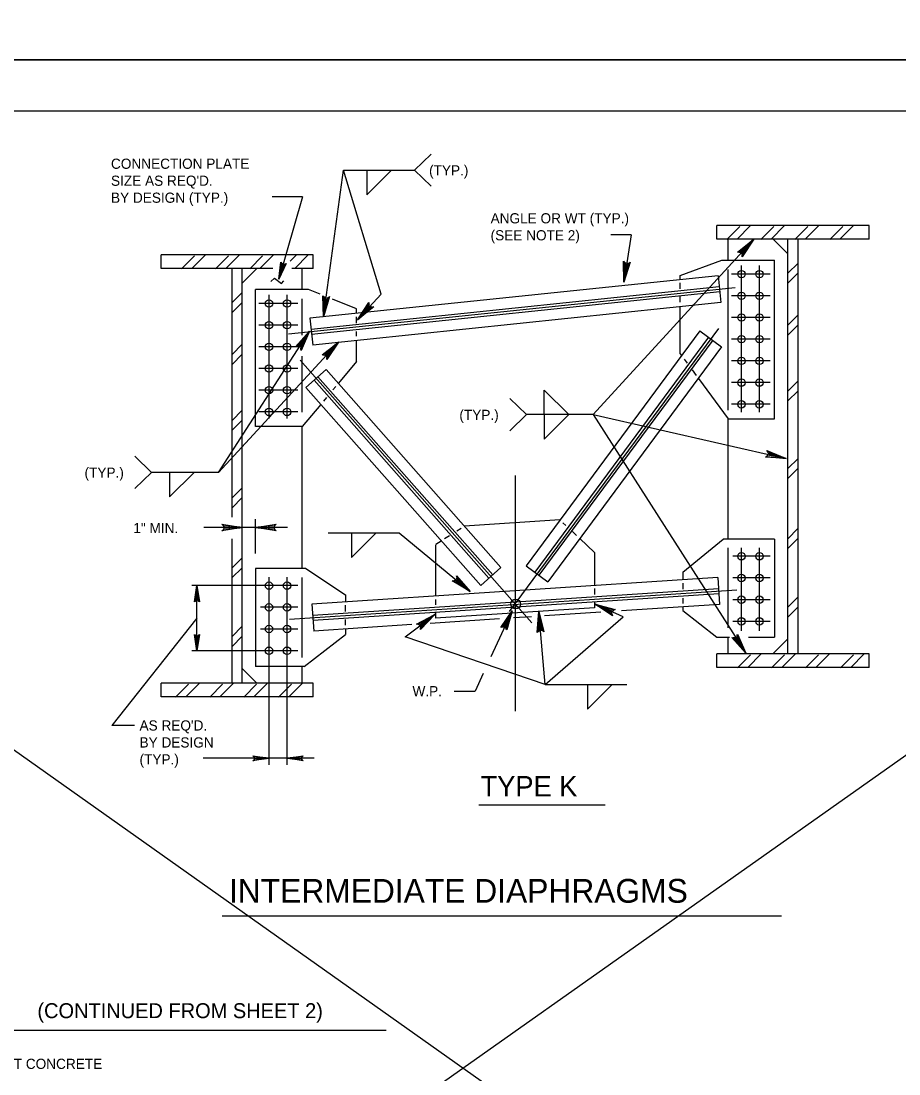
# Model space of a CAD drawing. Extents: x 634656 to 641360, y 298715 to 301183.
# Drawn here: x 634956.8 to 635215.5, y 299020.3 to 299330.4 of the extents above; entities that cross this region are included whole.
import ezdxf

# ---------------------------------------------------------------- set-up
doc = ezdxf.new("R2010")
doc.units = 0
for name, color, linetype in [('1', 7, 'Continuous'), ('2', 7, 'Continuous'), ('PLT-BNDY', 7, 'Continuous')]:
    doc.layers.add(name, color=color, linetype=linetype)

msp = doc.modelspace()

# ---------------------------------------------------------------- linework, layer by layer
at = {"layer": '1'}
for p, q in [((634656.46, 298718.13), (635518.79, 299326.83)), ((634661.92, 299322.77), (635521.53, 298714.94)), ((635045.96, 299243.34), (635051.84, 299286.49)), ((635063, 299249.96), (635051.84, 299286.49)), ((635051.84, 299286.49), (635072.82, 299286.49)), ((635039.82, 299278.64), (635032.8, 299254.4)), ((635206.76, 299270.17), (635161.92, 299270.17)), ((635161.92, 299266.17), (635161.92, 299270.17)), ((635168.63, 299269.89), (635164.81, 299266.08)), ((635171.83, 299270.17), (635167.83, 299266.17)), ((635178.66, 299269.89), (635174.85, 299266.08)), ((635181.86, 299270.17), (635177.86, 299266.17)), ((635188.69, 299269.89), (635184.88, 299266.08)), ((635191.9, 299270.17), (635187.9, 299266.17)), ((635198.96, 299269.89), (635195.15, 299266.08)), ((635202.17, 299270.17), (635198.17, 299266.17)), ((635206.76, 299266.17), (635206.76, 299270.17)), ((635125.47, 299214.49), (635172.79, 299266.16)), ((635136.63, 299267.42), (635134.46, 299253.48)), ((635206.76, 299266.17), (635161.92, 299266.17)), ((635165.17, 299260), (635165.17, 299266.17)), ((635182.84, 299261.84), (635178.52, 299266.17)), ((635182.84, 299144.06), (635182.84, 299266.17)), ((635185.84, 299144.06), (635185.84, 299266.17)), ((635042.94, 299261.53), (634998.1, 299261.53)), ((634998.1, 299257.53), (634998.1, 299261.53)), ((635011.16, 299261.53), (635007.17, 299257.53)), ((635021.2, 299261.53), (635017.2, 299257.53)), ((635031.23, 299261.53), (635027.23, 299257.53)), ((635038, 299261.53), (635036.16, 299259.69)), ((635041.5, 299261.53), (635037.5, 299257.53)), ((635042.94, 299257.53), (635042.94, 299261.53)), ((635007.96, 299261.25), (635004.15, 299257.44)), ((635017.99, 299261.25), (635014.18, 299257.44)), ((635028.03, 299261.25), (635024.22, 299257.44)), ((635151.11, 299255.46), (635163.37, 299260)), ((635163.37, 299260), (635178.89, 299260)), ((635169.12, 299215.26), (635169.12, 299258.45)), ((635174.43, 299215.26), (635174.43, 299258.45)), ((635178.89, 299213.23), (635178.89, 299260)), ((635185.84, 299259.14), (635182.84, 299256.13)), ((635030.99, 299257.53), (634998.1, 299257.53)), ((635019.02, 299184.26), (635019.02, 299257.53)), ((635022.02, 299253.2), (635026.35, 299257.53)), ((635022.02, 299135.42), (635022.02, 299257.53)), ((635042.94, 299257.53), (635036.65, 299257.53)), ((635039.69, 299251.36), (635039.69, 299257.53)), ((635162.27, 299255.42), (635041.96, 299242.92)), ((635151.11, 299254.26), (635151.11, 299255.46)), ((635162.27, 299255.42), (635163.09, 299247.5)), ((635165.17, 299215.79), (635165.17, 299257.28)), ((635177.57, 299255.89), (635166.16, 299255.89)), ((635185.84, 299256.21), (635182.84, 299253.21)), ((635042.3, 299239.69), (635162.61, 299252.19)), ((635151.11, 299251.55), (635151.11, 299253.36)), ((635022.02, 299250.49), (635019.02, 299247.49)), ((635025.97, 299210.98), (635025.97, 299251.36)), ((635041.58, 299251.36), (635025.97, 299251.36)), ((635029.92, 299213.33), (635029.92, 299249.81)), ((635035.23, 299213.33), (635035.23, 299249.81)), ((635035.65, 299238.26), (635167.26, 299251.94)), ((635044.95, 299250), (635041.58, 299251.36)), ((635042.45, 299238.23), (635162.76, 299250.73)), ((635063, 299249.96), (635055.98, 299242.37)), ((635151.11, 299247.6), (635151.11, 299249.33)), ((635177.57, 299249.5), (635166.16, 299249.5)), ((635022.02, 299247.57), (635019.02, 299244.57)), ((635038.37, 299247.25), (635026.96, 299247.25)), ((635039.69, 299237.87), (635039.69, 299248.63)), ((635163.09, 299247.5), (635042.78, 299235)), ((635055.71, 299245.65), (635048.63, 299248.52)), ((635151.11, 299232.4), (635151.11, 299246.26)), ((635041.96, 299242.92), (635042.78, 299235)), ((635055.71, 299244.35), (635055.71, 299245.65)), ((635055.71, 299241.4), (635055.71, 299243.29)), ((635177.57, 299243.11), (635166.16, 299243.11)), ((635185.84, 299243.87), (635182.84, 299240.87)), ((635038.37, 299240.86), (635026.96, 299240.86)), ((635162.34, 299239.91), (635100.66, 299156.56)), ((635185.84, 299240.95), (635182.84, 299237.95)), ((635015.01, 299197.49), (635041.89, 299239.06)), ((635055.71, 299237.57), (635055.71, 299239.02)), ((635156.86, 299239.2), (635105.66, 299170.01)), ((635159.47, 299237.27), (635108.27, 299168.08)), ((635156.86, 299239.2), (635163.26, 299234.46)), ((635177.57, 299236.72), (635166.16, 299236.72)), ((635015.01, 299197.49), (635050.38, 299235.88)), ((635022.02, 299235.23), (635019.02, 299232.23)), ((635038.37, 299234.47), (635026.96, 299234.47)), ((635055.71, 299230.13), (635055.71, 299236.35)), ((635160.65, 299236.39), (635109.45, 299167.2)), ((635163.26, 299234.46), (635112.06, 299165.27)), ((635022.02, 299232.31), (635019.02, 299229.31)), ((635039.08, 299230.5), (635107.35, 299153.2)), ((635039.69, 299215.26), (635039.69, 299231.76)), ((635151.11, 299232.4), (635151.47, 299231.9)), ((635152.29, 299230.79), (635153.11, 299229.66)), ((635177.57, 299230.32), (635166.16, 299230.32)), ((635038.37, 299228.07), (635026.96, 299228.07)), ((635046.77, 299227.75), (635040.81, 299222.48)), ((635046.77, 299227.75), (635098.26, 299169.45)), ((635055.71, 299230.13), (635050.41, 299223.8)), ((635154.59, 299227.65), (635155.78, 299226.02)), ((635043.24, 299224.63), (635094.72, 299166.33)), ((635044.34, 299225.6), (635095.82, 299167.3)), ((635156.44, 299225.12), (635165.17, 299213.23)), ((635185.84, 299224.45), (635182.84, 299221.45)), ((635038.37, 299221.68), (635026.96, 299221.68)), ((635040.81, 299222.48), (635092.29, 299164.18)), ((635049.6, 299222.83), (635048.74, 299221.8)), ((635177.57, 299223.93), (635166.16, 299223.93)), ((635185.84, 299221.53), (635182.84, 299218.53)), ((635046.89, 299219.59), (635045.96, 299218.48)), ((635022.02, 299215.81), (635019.02, 299212.81)), ((635038.37, 299215.29), (635026.96, 299215.29)), ((635045.14, 299217.5), (635039.69, 299210.98)), ((635177.57, 299217.54), (635166.16, 299217.54)), ((635022.02, 299212.89), (635019.02, 299209.89)), ((635125.47, 299214.49), (635105.75, 299214.49)), ((635125.47, 299214.49), (635170.4, 299144.22)), ((635125.47, 299214.49), (635182.35, 299201.6)), ((635165.17, 299213.23), (635178.89, 299213.23)), ((635165.17, 299177.8), (635165.17, 299213.23)), ((635039.69, 299210.98), (635025.97, 299210.98)), ((635039.69, 299169.16), (635039.69, 299210.98)), ((635185.84, 299201.61), (635182.84, 299198.61)), ((635015.01, 299197.49), (634995.29, 299197.49)), ((635102.43, 299196.62), (635102.43, 299127.15)), ((635185.84, 299198.69), (635182.84, 299195.69)), ((635022.02, 299192.97), (635019.02, 299189.97)), ((635022.02, 299190.05), (635019.02, 299187.05)), ((635025.97, 299173.6), (635025.97, 299183.69)), ((635086.49, 299181.01), (635085.22, 299180.19)), ((635115.63, 299183.48), (635087.48, 299181.65)), ((635116.53, 299182.64), (635117.42, 299181.81)), ((635185.78, 299180.95), (635182.78, 299177.95)), ((635019.02, 299135.42), (635019.02, 299177.96)), ((635047.33, 299179.68), (635068.31, 299179.68)), ((635068.31, 299179.68), (635089.23, 299162.41)), ((635083.11, 299178.83), (635081.66, 299177.89)), ((635119.32, 299180.03), (635120.56, 299178.87)), ((635121.49, 299178), (635125.87, 299173.91)), ((635151.86, 299168.14), (635163.71, 299177.8)), ((635178.89, 299177.8), (635163.71, 299177.8)), ((635178.89, 299177.8), (635178.89, 299148.95)), ((635185.78, 299178.03), (635182.78, 299175.03)), ((635079, 299176.17), (635079, 299161.18)), ((635080.66, 299177.25), (635079.06, 299176.21)), ((635165.17, 299151.74), (635165.17, 299175.29)), ((635169.12, 299150.85), (635169.12, 299175.24)), ((635174.43, 299150.85), (635174.43, 299175.24)), ((635021.96, 299172.31), (635018.96, 299169.31)), ((635125.87, 299173.91), (635125.87, 299164.22)), ((635177.58, 299172.78), (635166.57, 299172.78)), ((635021.96, 299169.39), (635018.96, 299166.39)), ((635025.97, 299169.16), (635025.97, 299140.31)), ((635040.8, 299169.16), (635025.97, 299169.16)), ((635040.8, 299169.16), (635052.46, 299161.38)), ((635098.26, 299169.45), (635092.29, 299164.18)), ((635105.66, 299170.01), (635112.06, 299165.27)), ((635029.92, 299111.33), (635029.92, 299166.6)), ((635035.23, 299111.33), (635035.23, 299166.6)), ((635039.69, 299142.97), (635039.69, 299166.51)), ((635162.19, 299166.51), (635042.58, 299158.71)), ((635151.86, 299168.14), (635151.86, 299165.83)), ((635162.19, 299166.51), (635162.71, 299158.56)), ((635177.58, 299166.39), (635166.57, 299166.39)), ((635038.38, 299164.14), (635007.15, 299164.14)), ((635008.68, 299144.96), (635008.68, 299164.14)), ((635035.93, 299154.29), (635167.78, 299162.88)), ((635042.79, 299155.48), (635162.4, 299163.27)), ((635125.87, 299163.32), (635125.87, 299161.51)), ((635151.86, 299164.88), (635151.86, 299163.07)), ((635042.89, 299154.01), (635162.5, 299161.8)), ((635052.46, 299161.38), (635052.46, 299159.36)), ((635079, 299160.03), (635079, 299158.47)), ((635125.87, 299159.46), (635125.87, 299157.58)), ((635151.86, 299160.4), (635151.86, 299158.92)), ((635177.58, 299160), (635166.57, 299160)), ((635185.84, 299160.8), (635182.84, 299157.8)), ((635038.38, 299157.75), (635027.37, 299157.75)), ((635042.58, 299158.71), (635043.1, 299150.77)), ((635052.46, 299156.54), (635052.46, 299158.35)), ((635125.87, 299157.58), (635079, 299154.53)), ((635079, 299156.17), (635079, 299154.53)), ((635101.53, 299156.74), (635095.32, 299143.2)), ((635111.32, 299135.05), (635109.38, 299156.51)), ((635127.73, 299156.28), (635111.06, 299155.2)), ((635134.23, 299154.97), (635125.98, 299158.64)), ((635162.71, 299158.56), (635133.8, 299156.68)), ((635151.86, 299157.86), (635151.86, 299156.77)), ((635151.86, 299156.77), (635161.87, 299148.95)), ((635185.84, 299157.88), (635182.84, 299154.87)), ((635008.68, 299154.55), (634983.57, 299122.91)), ((635052.46, 299152.47), (635052.46, 299154.16)), ((635070.04, 299149.07), (635078.82, 299155.68)), ((635097.87, 299154.34), (635077.42, 299153.01)), ((635107.24, 299154.95), (635101.99, 299154.61)), ((635111.32, 299135.05), (635134.23, 299154.97)), ((635177.58, 299153.61), (635166.57, 299153.61)), ((635022.02, 299152.16), (635019.02, 299149.15)), ((635038.38, 299151.36), (635027.37, 299151.36)), ((635040.3, 299140.31), (635052.46, 299149.71)), ((635072.01, 299152.66), (635043.1, 299150.77)), ((635052.46, 299151.38), (635052.46, 299149.71)), ((635022.02, 299149.23), (635019.02, 299146.23)), ((635111.32, 299135.05), (635070.04, 299149.07)), ((635161.87, 299148.95), (635165.62, 299148.95)), ((635165.17, 299144.06), (635165.17, 299148.95)), ((635171.2, 299148.95), (635178.89, 299148.95)), ((635178.48, 299144.1), (635182.8, 299148.43)), ((635038.38, 299144.96), (635007.15, 299144.96)), ((635206.76, 299144.06), (635161.92, 299144.06)), ((635161.92, 299140.06), (635161.92, 299144.06)), ((635171.79, 299143.78), (635167.98, 299139.96)), ((635203.47, 299144.06), (635169.43, 299144.06)), ((635174.99, 299144.06), (635170.99, 299140.06)), ((635181.82, 299143.78), (635178.01, 299139.96)), ((635185.02, 299144.06), (635181.02, 299140.06)), ((635191.85, 299143.78), (635188.04, 299139.96)), ((635195.06, 299144.06), (635191.06, 299140.06)), ((635202.13, 299143.78), (635198.31, 299139.96)), ((635205.33, 299144.06), (635201.33, 299140.06)), ((635206.76, 299140.06), (635206.76, 299144.06)), ((635022.02, 299139.74), (635026.35, 299135.42)), ((635040.3, 299140.31), (635025.97, 299140.31)), ((635039.69, 299135.42), (635039.69, 299140.31)), ((635093.04, 299138.22), (635090.65, 299133.01)), ((635206.76, 299140.06), (635161.92, 299140.06)), ((635042.94, 299135.42), (634998.1, 299135.42)), ((634998.1, 299131.42), (634998.1, 299135.42)), ((635006.2, 299135.14), (635002.39, 299131.32)), ((635037.89, 299135.42), (635003.85, 299135.42)), ((635009.41, 299135.42), (635005.41, 299131.42)), ((635016.24, 299135.14), (635012.43, 299131.32)), ((635019.44, 299135.42), (635015.44, 299131.42)), ((635026.27, 299135.14), (635022.46, 299131.32)), ((635029.47, 299135.42), (635025.48, 299131.42)), ((635036.54, 299135.14), (635032.73, 299131.32)), ((635039.75, 299135.42), (635035.75, 299131.42)), ((635042.94, 299131.42), (635042.94, 299135.42)), ((635111.32, 299135.05), (635135.39, 299135.05)), ((635042.94, 299131.42), (634998.1, 299131.42)), ((635084.45, 299133.01), (635090.65, 299133.01)), ((634990.28, 299122.91), (634983.57, 299122.91)), ((635029.92, 299113.28), (635010.55, 299113.28)), ((635035.23, 299113.28), (635029.92, 299113.28)), ((635043.19, 299113.28), (635035.23, 299113.28))]:
    msp.add_line(p, q, dxfattribs=at)
for points in [[(635168.34, 299262.38), (635168.79, 299262.25), (635172.79, 299266.16), (635168.34, 299262.38), (635167.95, 299262.33), (635172.79, 299266.16), (635169.23, 299261.86), (635169.39, 299261.43), (635172.79, 299266.16), (635169.39, 299261.01), (635169.39, 299261.43)], [(635034.7, 299258.82), (635034.32, 299258.74), (635032.8, 299254.4), (635034.7, 299258.82), (635034.97, 299258.99), (635032.8, 299254.4), (635033.86, 299258.87), (635033.57, 299259.13), (635032.8, 299254.4), (635033.43, 299259.44), (635033.57, 299259.13)], [(635136.04, 299259.11), (635135.6, 299258.96), (635134.46, 299253.48), (635136.04, 299259.11), (635136.34, 299259.36), (635134.46, 299253.48), (635135.02, 299259.04), (635134.64, 299259.3), (635134.46, 299253.48), (635134.41, 299259.65), (635134.64, 299259.3)], [(635030.49, 299253.75), (635031.49, 299254.65), (635033.6, 299253.15), (635034.3, 299253.95)], [(635047.46, 299248.98), (635047.02, 299248.83), (635045.96, 299243.34), (635047.46, 299248.98), (635047.76, 299249.24), (635045.96, 299243.34), (635046.44, 299248.9), (635046.05, 299249.16), (635045.96, 299243.34), (635045.82, 299249.51), (635046.05, 299249.16)], [(635060.42, 299246.16), (635059.97, 299246.29), (635055.98, 299242.37), (635060.42, 299246.16), (635060.81, 299246.21), (635055.98, 299242.37), (635059.53, 299246.68), (635059.36, 299247.11), (635055.98, 299242.37), (635059.37, 299247.53), (635059.36, 299247.11)], [(635038.13, 299234.59), (635038.6, 299234.54), (635041.89, 299239.06), (635038.13, 299234.59), (635037.75, 299234.48), (635041.89, 299239.06), (635039.09, 299234.23), (635039.33, 299233.83), (635041.89, 299239.06), (635039.39, 299233.42), (635039.33, 299233.83)], [(635045.92, 299232.1), (635046.37, 299231.98), (635050.38, 299235.88), (635045.92, 299232.1), (635045.53, 299232.06), (635050.38, 299235.88), (635046.81, 299231.59), (635046.97, 299231.15), (635050.38, 299235.88), (635046.96, 299230.74), (635046.97, 299231.15)], [(635176.85, 299203.59), (635176.97, 299203.14), (635182.35, 299201.6), (635176.85, 299203.59), (635176.62, 299203.91), (635182.35, 299201.6), (635176.85, 299202.57), (635176.56, 299202.21), (635182.35, 299201.6), (635176.19, 299202.01), (635176.56, 299202.21)], [(635016.34, 299181.99), (635016.56, 299181.57), (635022.14, 299181.26), (635016.34, 299181.99), (635016.04, 299182.24), (635022.14, 299181.26), (635016.56, 299180.99), (635016.36, 299180.57), (635022.14, 299181.26), (635016.04, 299180.29), (635016.36, 299180.57)], [(635031.77, 299180.53), (635031.56, 299180.95), (635025.97, 299181.26), (635031.77, 299180.53), (635032.07, 299180.28), (635025.97, 299181.26), (635031.55, 299181.54), (635031.76, 299181.95), (635025.97, 299181.26), (635032.07, 299182.23), (635031.76, 299181.95)], [(635085.22, 299166.66), (635085.12, 299166.2), (635089.23, 299162.41), (635085.22, 299166.66), (635085.15, 299167.05), (635089.23, 299162.41), (635084.75, 299165.75), (635084.33, 299165.55), (635089.23, 299162.41), (635083.91, 299165.54), (635084.33, 299165.55)], [(635008.11, 299159.6), (635008.44, 299159.77), (635008.68, 299164.14), (635008.11, 299159.6), (635007.91, 299159.37), (635008.68, 299164.14), (635008.9, 299159.77), (635009.22, 299159.61), (635008.68, 299164.14), (635009.44, 299159.37), (635009.22, 299159.61)], [(635098.6, 299152), (635099.05, 299152.02), (635101.53, 299156.74), (635098.6, 299152), (635098.26, 299151.85), (635101.53, 299156.74), (635099.55, 299151.79), (635099.83, 299151.45), (635101.53, 299156.74), (635099.95, 299151.07), (635099.83, 299151.45)], [(635109.18, 299150.67), (635109.58, 299150.92), (635109.38, 299156.51), (635109.18, 299150.67), (635108.95, 299150.35), (635109.38, 299156.51), (635110.16, 299150.98), (635110.59, 299150.81), (635109.38, 299156.51), (635110.9, 299150.52), (635110.59, 299150.81)], [(635130.99, 299155.64), (635130.96, 299156.11), (635125.98, 299158.64), (635130.99, 299155.64), (635131.16, 299155.28), (635125.98, 299158.64), (635131.19, 299156.64), (635131.55, 299156.94), (635125.98, 299158.64), (635131.94, 299157.07), (635131.55, 299156.94)], [(635073.73, 299152.8), (635074.16, 299152.59), (635078.82, 299155.68), (635073.73, 299152.8), (635073.34, 299152.82), (635078.82, 299155.68), (635074.51, 299152.12), (635074.59, 299151.67), (635078.82, 299155.68), (635074.51, 299151.26), (635074.59, 299151.67)], [(635009.25, 299149.5), (635008.92, 299149.34), (635008.68, 299144.96), (635009.25, 299149.5), (635009.45, 299149.74), (635008.68, 299144.96), (635008.46, 299149.33), (635008.14, 299149.49), (635008.68, 299144.96), (635007.92, 299149.74), (635008.14, 299149.49)], [(635167.89, 299149.5), (635167.65, 299149.09), (635170.4, 299144.22), (635167.89, 299149.5), (635167.94, 299149.88), (635170.4, 299144.22), (635167.16, 299148.77), (635166.7, 299148.72), (635170.4, 299144.22), (635166.3, 299148.83), (635166.7, 299148.72)], [(635025.38, 299113.85), (635025.55, 299113.52), (635029.92, 299113.28), (635025.38, 299113.85), (635025.15, 299114.05), (635029.92, 299113.28), (635025.55, 299113.07), (635025.4, 299112.74), (635029.92, 299113.28), (635025.15, 299112.52), (635025.4, 299112.74)], [(635039.77, 299112.71), (635039.6, 299113.04), (635035.23, 299113.28), (635039.77, 299112.71), (635040.01, 299112.51), (635035.23, 299113.28), (635039.6, 299113.5), (635039.76, 299113.82), (635035.23, 299113.28), (635040.01, 299114.04), (635039.76, 299113.82)]]:
    msp.add_lwpolyline(points, dxfattribs=at)
for centre, radius in [((635169.12, 299255.89), 1.09), ((635174.43, 299255.89), 1.09), ((635169.12, 299249.5), 1.09), ((635174.43, 299249.5), 1.09), ((635029.92, 299247.25), 1.09), ((635035.23, 299247.25), 1.09), ((635169.12, 299243.11), 1.09), ((635174.43, 299243.11), 1.09), ((635029.92, 299240.86), 1.09), ((635035.23, 299240.86), 1.09), ((635169.12, 299236.72), 1.09), ((635174.43, 299236.72), 1.09), ((635029.92, 299234.47), 1.09), ((635035.23, 299234.47), 1.09), ((635169.12, 299230.32), 1.09), ((635174.43, 299230.32), 1.09), ((635029.92, 299228.07), 1.09), ((635035.23, 299228.07), 1.09), ((635169.12, 299223.93), 1.09), ((635174.43, 299223.93), 1.09), ((635029.92, 299221.68), 1.09), ((635035.23, 299221.68), 1.09), ((635169.12, 299217.54), 1.09), ((635174.43, 299217.54), 1.09), ((635029.92, 299215.29), 1.09), ((635035.23, 299215.29), 1.09), ((635169.12, 299172.78), 1.09), ((635174.43, 299172.78), 1.09), ((635029.92, 299164.14), 1.09), ((635035.23, 299164.14), 1.09), ((635169.12, 299166.39), 1.09), ((635174.43, 299166.39), 1.09), ((635102.59, 299158.72), 1.45), ((635169.12, 299160), 1.09), ((635174.43, 299160), 1.09), ((635029.92, 299157.75), 1.09), ((635035.23, 299157.75), 1.09), ((635169.12, 299153.61), 1.09), ((635174.43, 299153.61), 1.09), ((635029.92, 299151.36), 1.09), ((635035.23, 299151.36), 1.09), ((635029.92, 299144.96), 1.09), ((635035.23, 299144.96), 1.09)]:
    msp.add_circle(centre, radius, dxfattribs=at)
at = {"layer": '2'}
for p, q in [((634706.42, 299303.99), (635492.42, 299303.99)), ((635058.72, 299286.49), (635058.72, 299279.24)), ((635058.72, 299279.24), (635065.97, 299286.49)), ((635039.82, 299278.64), (635030.8, 299278.64)), ((635136.63, 299267.42), (635130.66, 299267.42)), ((635111.03, 299214.49), (635111.03, 299221.74)), ((635111.03, 299221.74), (635118.28, 299214.49)), ((635111.03, 299214.49), (635111.03, 299207.24)), ((635111.03, 299207.24), (635118.28, 299214.49)), ((635000.57, 299197.48), (635000.57, 299190.24)), ((635000.57, 299190.24), (635007.82, 299197.48)), ((635022.14, 299181.26), (635010.68, 299181.26)), ((635025.97, 299181.26), (635022.14, 299181.26)), ((635035.38, 299181.26), (635025.97, 299181.26)), ((635054.2, 299179.68), (635054.2, 299172.44)), ((635054.2, 299172.44), (635061.45, 299179.68)), ((635123.78, 299135.05), (635123.78, 299127.8)), ((635123.78, 299127.8), (635131.03, 299135.05)), ((635091.77, 299099.54), (635129, 299099.54)), ((635016.12, 299066.86), (635180.98, 299066.86)), ((634719.06, 299033.25), (635064.45, 299033.25))]:
    msp.add_line(p, q, dxfattribs=at)
for points in [[(635077.7, 299291.24), (635072.82, 299286.49), (635077.7, 299281.74)], [(635100.87, 299219.24), (635105.75, 299214.49), (635100.87, 299209.74)], [(634990.41, 299202.23), (634995.29, 299197.48), (634990.41, 299192.74)]]:
    msp.add_lwpolyline(points, dxfattribs=at)
at = {"layer": 'PLT-BNDY'}
for points in [[(634666.42, 299912.99), (635507.42, 299912.99), (635507.42, 299318.99), (634666.42, 299318.99)], [(634666.42, 299318.99), (635507.42, 299318.99), (635507.42, 298724.99), (634666.42, 298724.99)]]:
    msp.add_lwpolyline(points, close=True, dxfattribs=at)

# ---------------------------------------------------------------- texts
at = {"layer": '1'}
for s, height, p in [('CONNECTION PLATE', 2.9999, (634983.35, 299286.89)), ("SIZE AS REQ'D.", 2.9999, (634983.35, 299281.89)), ('BY DESIGN (TYP.)', 2.9999, (634983.35, 299276.89)), ('1" MIN.', 3, (634989.93, 299179.59)), ('W.P.', 3, (635072.19, 299131.55)), ("AS REQ'D.", 3, (634991.76, 299121.46)), ('BY DESIGN', 3, (634991.76, 299116.46)), ('(TYP.)', 3, (634991.76, 299111.46)), ('(CONTINUED FROM SHEET 2)', 4.4062, (634961.66, 299036.75)), ('THE DIAPHRAGM TOP CHORD SHOULD BE DESIGNED TO CARRY A PORTION OF THE DEAD LOAD OF THE WET CONCRETE', 2.9999, (634741.16, 299021.8))]:
    msp.add_text(s, height=height, dxfattribs=at).set_placement(p)
at = {"layer": '2'}
for s, height, p in [('(TYP.)', 3, (635077.08, 299284.93)), ('ANGLE OR WT (TYP.)', 2.9999, (635095.21, 299270.82)), ('(SEE NOTE 2)', 2.9999, (635095.21, 299265.82)), ('(TYP.)', 3, (635086.01, 299212.93)), ('(TYP.)', 3, (634975.55, 299195.92)), ('TYPE K', 6, (635092.26, 299102.05)), ('INTERMEDIATE DIAPHRAGMS', 7, (635018.11, 299070.75))]:
    msp.add_text(s, height=height, dxfattribs=at).set_placement(p)

doc.saveas('drawing.dxf')
